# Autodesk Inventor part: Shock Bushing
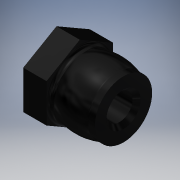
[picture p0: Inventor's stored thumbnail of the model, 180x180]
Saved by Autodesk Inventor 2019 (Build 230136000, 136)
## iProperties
Shininess: 50.0
Compacted: True
Length Units: 11272
Angle Units: 11279
Time Units: 11290
Mass Units: 11286
Length Display Precision: 4
Angle Display Precision: 2
Company: Autodesk
Created: 2000-07
Part Number: Shock Bushing
Project: Inventor Samples
Document SubType Name: Modeling
Designer: Autodesk, Inc.
Density: 1.13 g/cm^3
Mass: 0.177954 g
Surface Area: 2.27867 cm^2
Volume: 0.157481 cm^3
Material: Nylon-6/6
Appearance: Glossy - Black
Density: 0.0
Volumn: 0.0
Area: 0.0
PropertySet Name: Model Information
Control State: 0
Master: False
Checked Out: False
Checked Out Date: 2018-05-30
Last Check In Date: 2018-05-30
Author: Autodesk, Inc.
Revision Number: A
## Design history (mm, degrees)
node "Revolution1" dims "d9" = 90 deg
  sketch "Sketch3"
    geometry: L1 (-7.537, 0.965)-(-13.29, 0.965); L2 (-13.29, 0.965)-(-13.29, 2.895); L3 (-13.29, 2.895)-(-11.068, 2.895); L4 (-11.068, 2.895)-(-11.068, 2.452); L5 (-7.537, 0.965)-(-7.537, 2.452); L6 (-13.29, -0.28)-(-7.606, -0.28); A1 r 5.08 centre (-9.303, -2.312) between (-7.537, 2.452) and (-11.068, 2.452)
    constraints: 12 end point, 3 parallel, 2 perpendicular, 2 point on circle, 1 centre point, 1 horizontal, 1 horizontal alignment, 1 point on line, 1 other
    dimensions: "d1" = 2.4892 diameter of L1 L6; "d2" = 6.35 diameter of L3 L6; "d3" = 2.2225 distance of L2.end L3.end; "d4" = 6.096 dimension on A1 L6; "d7" = 3.9878 distance from line of A1.centre L2; "d10" = 5.08 radius of A1
node "Extrusion1" dims "d14" = 25.4, "d15" = 0
  sketch "Sketch4"
    geometry: L1 (-3.175, -1.833)-(-3.175, 1.833); L2 (-3.175, 1.833)-(0, 3.666); L3 (0, 3.666)-(3.175, 1.833); L4 (3.175, 1.833)-(3.175, -1.833); L5 (3.175, -1.833)-(0, -3.666); L6 (0, -3.666)-(-3.175, -1.833); C1 r 3.175 at (0, 0) reference
    constraints: 12 end point, 6 tangent, 3 parallel, 2 equal length, 1 vertical
node "Extrusion2" dims "d17" = 0.635, "d18" = 0
  sketch "Sketch5"
    geometry: C1 r 1.245 at (0, 0) reference; C2 r 2.731 at (0, 0) reference
node "Fillet1" dims "d16" = 0.381
node "Chamfer1" dims "d12" = 0.381, "d13" = 0.381, "d19" = 45 deg
body "Solid1"
other parameters: "d11" = 6.0706 (derived), "d20" = 0
